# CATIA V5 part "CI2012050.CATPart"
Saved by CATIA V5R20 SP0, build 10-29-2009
Part number: CI2012050
Bounding box of the stored display mesh (mm): x -12 to 12, y -9.679 to 68, z -16.11 to 13.284
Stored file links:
  C:\Users\Raffaele\Desktop\3D X SITO CF\BOLEX\19-INCLINED ASSEMBLY REF_CI\CI2012050.CATPart

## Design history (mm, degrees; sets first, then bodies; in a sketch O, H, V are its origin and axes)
Set1
  DatumSurface1 to DatumSurface16 "MANIFOLD_SOLID_BREP #377"
  DatumSurface17 to DatumSurface39 "MANIFOLD_SOLID_BREP #1096"
Body1 (main body)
